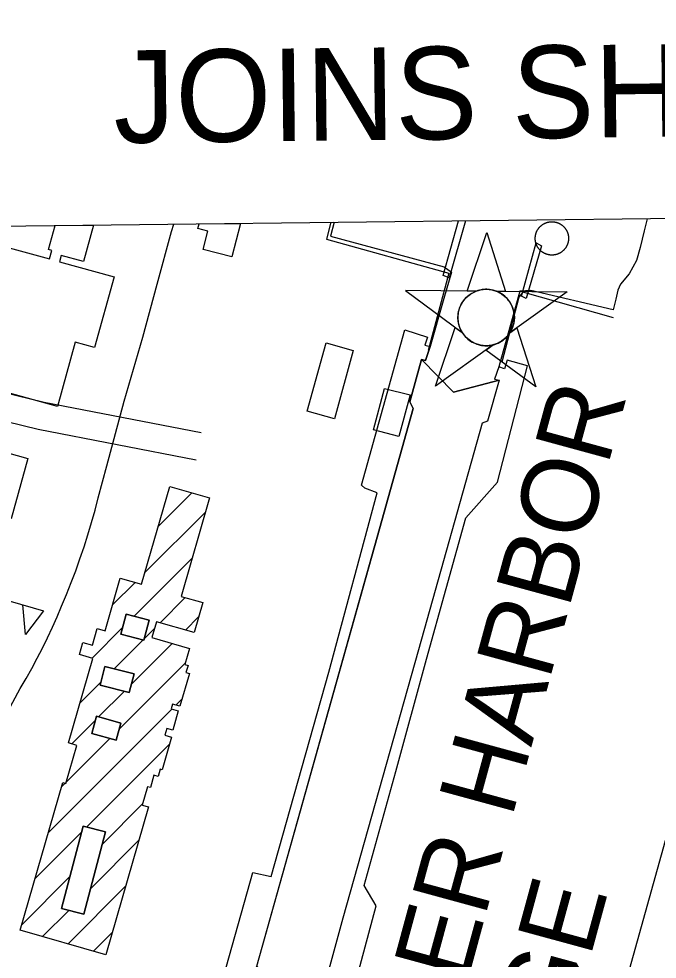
# Model space of a CAD drawing. Extents: x 3677843 to 3715951, y 511991 to 537744.
# Drawn here: x 3694073 to 3694764, y 534934 to 535951 of the extents above; entities that cross this region are included whole.
import ezdxf

# ---------------------------------------------------------------- set-up
doc = ezdxf.new("R2010")
doc.units = 0
for name, color, linetype in [('V-ANNO-TEXT', 7, 'Continuous'), ('V-BLDG-OTLN', 7, 'Continuous'), ('V-CHAN-DOCK', 7, 'Continuous'), ('V-CHAN-NAID', 7, 'Continuous'), ('V-GRID-FRAM', 7, 'Continuous'), ('V-RAIL-TRAK', 7, 'Continuous'), ('V-RIVR-GAGE-IDEN', 7, 'Continuous'), ('V-ROAD-CNTR', 7, 'Continuous'), ('V-RRAP-FSHR', 7, 'Continuous'), ('V-TOPO-SHOR', 7, 'Continuous'), ('V-TRAN-LOCK', 7, 'Continuous')]:
    doc.layers.add(name, color=color, linetype=linetype)

msp = doc.modelspace()

# ---------------------------------------------------------------- linework, layer by layer
at = {"layer": 'V-BLDG-OTLN'}
for p, q in [((3694266.5, 535724.1), (3694267.8, 535729.2)), ((3694267.8, 535729.2), (3694312.6, 535729.7)), ((3694312.6, 535729.7), (3694303.2, 535693.5)), ((3694105, 535701.3), (3694112.2, 535727.4)), ((3694112.2, 535727.4), (3694153.6, 535727.9)), ((3694153.6, 535727.9), (3694142.7, 535688.4)), ((3694277.3, 535721.3), (3694266.5, 535724.1)), ((3694272.2, 535701.5), (3694277.3, 535721.3)), ((3694062.3, 535703.3), (3694106.2, 535691.2)), ((3694108.7, 535700.3), (3694105, 535701.3)), ((3694106.2, 535691.2), (3694108.7, 535700.3)), ((3694303.2, 535693.5), (3694272.2, 535701.5)), ((3694118.6, 535695), (3694116.7, 535688.3)), ((3694116.7, 535688.3), (3694175.9, 535672)), ((3694142.7, 535688.4), (3694118.6, 535695)), ((3694175.9, 535672), (3694154.8, 535595.4)), ((3694133.8, 535601.2), (3694114.7, 535531.8)), ((3694154.8, 535595.4), (3694133.8, 535601.2)), ((3694114.7, 535531.8), (3693912.5, 535587.5)), ((3694223.6, 535401.8), (3694260.2, 535438.4)), ((3694209.3, 535352.1), (3694275, 535417.9)), ((3694197.5, 535305), (3694260.7, 535368.2)), ((3694174.2, 535317.1), (3694198.7, 535341.5)), ((3694041.8, 535327.5), (3694099.4, 535310.6)), ((3694225.6, 535297.7), (3694252.9, 535325)), ((3694253.1, 535289.9), (3694267.4, 535304.2)), ((3694152.1, 535259.6), (3694185.1, 535292.6)), ((3694208.7, 535280.9), (3694219.7, 535291.8)), ((3694176, 535248.1), (3694207.2, 535279.3)), ((3694194.6, 535231.4), (3694238.7, 535275.5)), ((3694181.4, 535182.8), (3694253.1, 535254.5)), ((3694139, 535211.1), (3694161.8, 535233.9)), ((3694159.2, 535196), (3694187.1, 535223.9)), ((3694242.8, 535208.9), (3694249.6, 535215.6)), ((3694104.6, 535070.7), (3694238.5, 535204.6)), ((3694130.1, 535166.8), (3694155.7, 535192.4)), ((3694124.2, 535125.6), (3694171.3, 535172.8)), ((3694146.3, 535077.1), (3694235.9, 535166.6)), ((3694119, 535120.4), (3694122.9, 535124.3)), ((3694163.3, 535058.6), (3694206.8, 535102.2)), ((3694090.3, 535021), (3694140.7, 535071.4)), ((3694150.7, 535010.7), (3694202.7, 535062.7)), ((3694076, 534971.3), (3694128.1, 535023.5)), ((3694126.1, 534950.7), (3694188.4, 535013.1)), ((3694098.6, 534958.6), (3694126.9, 534986.9)), ((3694153.5, 534942.8), (3694174.1, 534963.4))]:
    msp.add_line(p, q, dxfattribs=at)
for points in [[(3694434.7, 535592.3), (3694414.3, 535518.4), (3694384.8, 535526.5), (3694405.2, 535600.4)], [(3694496.2, 535544.2), (3694483.9, 535499.2), (3694456.4, 535506.6), (3694468.5, 535551.3)], [(3694029, 535285.8), (3693894.8, 535323.5), (3693890.9, 535309.5), (3693861.1, 535317.8), (3693876.4, 535372.1), (3693851.4, 535379.1), (3693855.4, 535393.5), (3693880.3, 535386.5), (3693918.2, 535521.6), (3694082.7, 535475.4), (3694064.4, 535410.4), (3693929.1, 535448.5), (3693912, 535387.4), (3694046.9, 535349.4)], [(3694257.6, 535270.2), (3694252.6, 535252.8), (3694255.9, 535251.8), (3694253.7, 535244.1), (3694257.5, 535243), (3694247.2, 535207.6), (3694239, 535209.9), (3694237.6, 535204.9), (3694245.4, 535202.6), (3694239.3, 535181.6), (3694232.9, 535183.4), (3694230.8, 535176.4), (3694238.1, 535174.3), (3694227.9, 535138.9), (3694225.9, 535139.5), (3694223.7, 535131.6), (3694219, 535133), (3694215.2, 535119.7), (3694212.1, 535120.6), (3694206.4, 535100.8), (3694213.1, 535098.8), (3694167, 534938.9), (3694074.3, 534965.6), (3694120.3, 535125), (3694123.7, 535124), (3694135.6, 535165.2), (3694126.5, 535167.9), (3694152.9, 535259.3), (3694138.4, 535263.5), (3694142.2, 535276.7), (3694152.4, 535273.8), (3694157.6, 535291.8), (3694166.2, 535289.3), (3694182.6, 535346.2), (3694205.7, 535339.5), (3694236.2, 535445.3), (3694279.3, 535432.8), (3694248.6, 535326.3), (3694271.8, 535319.6), (3694262.5, 535287.2), (3694221.7, 535298.8), (3694216.8, 535281.8)], [(3694099.4, 535310.6), (3694079.9, 535285.1), (3694077.2, 535317.1)], [(3694208.2, 535279.1), (3694214, 535300.6), (3694189, 535307.3), (3694183.2, 535285.7)], [(3694208.2, 535279.1), (3694183.2, 535285.7), (3694189, 535307.3), (3694214, 535300.6)], [(3694197.5, 535242.6), (3694166, 535250.6), (3694160.9, 535230.5), (3694192.4, 535222.5)], [(3694197.5, 535242.6), (3694192.4, 535222.5), (3694160.9, 535230.5), (3694166, 535250.6)], [(3694183.2, 535189.4), (3694156.8, 535196.7), (3694151.7, 535178.2), (3694178.1, 535170.9)], [(3694183.2, 535189.4), (3694178.1, 535170.9), (3694151.7, 535178.2), (3694156.8, 535196.7)], [(3694166.7, 535071.7), (3694142.5, 535078.1), (3694119, 534989), (3694143.3, 534982.6)], [(3694166.7, 535071.7), (3694143.3, 534982.6), (3694119, 534989), (3694142.5, 535078.1)]]:
    msp.add_lwpolyline(points, close=True, dxfattribs=at)
at = {"layer": 'V-CHAN-DOCK'}
for points in [[(3694631.5, 535714), (3694631.6, 535714.4), (3694631.6, 535714.7), (3694631.6, 535715), (3694631.6, 535715.3), (3694631.7, 535715.6), (3694631.7, 535715.9), (3694631.8, 535716.2), (3694631.8, 535716.6), (3694631.9, 535716.9), (3694631.9, 535717.2), (3694632, 535717.5), (3694632.1, 535717.8), (3694632.1, 535718.1), (3694632.2, 535718.4), (3694632.3, 535718.7), (3694632.4, 535719), (3694632.5, 535719.3), (3694632.6, 535719.6), (3694632.7, 535719.9), (3694632.8, 535720.2), (3694633, 535720.5), (3694633.1, 535720.8), (3694633.2, 535721), (3694633.3, 535721.3), (3694633.5, 535721.6), (3694633.6, 535721.9), (3694633.8, 535722.2), (3694633.9, 535722.4), (3694634.1, 535722.7), (3694634.3, 535723), (3694634.4, 535723.2), (3694634.6, 535723.5), (3694634.8, 535723.8), (3694635, 535724), (3694635.1, 535724.3), (3694635.3, 535724.5), (3694635.5, 535724.8), (3694635.7, 535725), (3694635.9, 535725.3), (3694636.1, 535725.5), (3694636.4, 535725.7), (3694636.6, 535726), (3694636.8, 535726.2), (3694637, 535726.4), (3694637.2, 535726.6), (3694637.5, 535726.8), (3694637.7, 535727), (3694638, 535727.2), (3694638.2, 535727.4), (3694638.4, 535727.6), (3694638.7, 535727.8), (3694638.9, 535728), (3694639.2, 535728.2), (3694639.5, 535728.4), (3694639.7, 535728.6), (3694640, 535728.7), (3694640.2, 535728.9), (3694640.5, 535729.1), (3694640.8, 535729.2), (3694641.1, 535729.4), (3694641.4, 535729.5), (3694641.6, 535729.7), (3694641.9, 535729.8), (3694642.2, 535729.9), (3694642.5, 535730), (3694642.8, 535730.2), (3694643.1, 535730.3), (3694643.4, 535730.4), (3694643.7, 535730.5), (3694644, 535730.6), (3694644.3, 535730.7), (3694644.6, 535730.8), (3694644.9, 535730.9), (3694645.2, 535730.9), (3694645.5, 535731), (3694645.8, 535731.1), (3694646.1, 535731.2), (3694646.4, 535731.2), (3694646.7, 535731.3), (3694647, 535731.3), (3694647.3, 535731.4), (3694647.6, 535731.4), (3694648, 535731.4), (3694648.3, 535731.4), (3694648.6, 535731.5), (3694648.9, 535731.5), (3694649.2, 535731.5), (3694649.5, 535731.5), (3694649.8, 535731.5), (3694650.2, 535731.5), (3694650.5, 535731.5), (3694650.8, 535731.5), (3694651.1, 535731.4), (3694651.4, 535731.4), (3694651.7, 535731.4), (3694652, 535731.3), (3694652.4, 535731.3), (3694652.7, 535731.2), (3694653, 535731.2), (3694653.3, 535731.1)], [(3694653.3, 535731.1), (3694653.6, 535731), (3694653.9, 535731), (3694654.2, 535730.9), (3694654.5, 535730.8), (3694654.8, 535730.7), (3694655.1, 535730.6), (3694655.4, 535730.5), (3694655.7, 535730.4), (3694656, 535730.3), (3694656.3, 535730.2), (3694656.6, 535730.1), (3694656.9, 535730), (3694657.2, 535729.8), (3694657.4, 535729.7), (3694657.7, 535729.5), (3694658, 535729.4), (3694658.3, 535729.3), (3694658.6, 535729.1), (3694658.8, 535728.9), (3694659.1, 535728.8), (3694659.4, 535728.6), (3694659.6, 535728.4), (3694659.9, 535728.3), (3694660.1, 535728.1), (3694660.4, 535727.9), (3694660.6, 535727.7), (3694660.9, 535727.5), (3694661.1, 535727.3), (3694661.4, 535727.1), (3694661.6, 535726.9), (3694661.8, 535726.7), (3694662.1, 535726.5), (3694662.3, 535726.2), (3694662.5, 535726), (3694662.7, 535725.8), (3694662.9, 535725.6), (3694663.2, 535725.3), (3694663.4, 535725.1), (3694663.6, 535724.8), (3694663.8, 535724.6), (3694664, 535724.3), (3694664.1, 535724.1), (3694664.3, 535723.8), (3694664.5, 535723.6), (3694664.7, 535723.3), (3694664.8, 535723.1), (3694665, 535722.8), (3694665.2, 535722.5), (3694665.3, 535722.2), (3694665.5, 535722), (3694665.6, 535721.7), (3694665.8, 535721.4), (3694665.9, 535721.1), (3694666, 535720.8), (3694666.2, 535720.5), (3694666.3, 535720.3), (3694666.4, 535720), (3694666.5, 535719.7), (3694666.6, 535719.4), (3694666.7, 535719.1)], [(3694666.7, 535719.1), (3694666.8, 535718.8), (3694666.9, 535718.5), (3694667, 535718.2), (3694667.1, 535717.9), (3694667.1, 535717.6), (3694667.2, 535717.2), (3694667.3, 535716.9), (3694667.3, 535716.6), (3694667.4, 535716.3), (3694667.4, 535716), (3694667.5, 535715.7), (3694667.5, 535715.4), (3694667.5, 535715.1), (3694667.6, 535714.8), (3694667.6, 535714.4), (3694667.6, 535714.1), (3694667.6, 535713.8), (3694667.6, 535713.5), (3694667.6, 535713.2), (3694667.6, 535712.9), (3694667.6, 535712.6), (3694667.6, 535712.2), (3694667.5, 535711.9), (3694667.5, 535711.6), (3694667.5, 535711.3), (3694667.4, 535711), (3694667.4, 535710.7), (3694667.3, 535710.4), (3694667.3, 535710.1), (3694667.2, 535709.8), (3694667.2, 535709.4), (3694667.1, 535709.1), (3694667, 535708.8), (3694666.9, 535708.5), (3694666.8, 535708.2), (3694666.7, 535707.9), (3694666.6, 535707.6), (3694666.5, 535707.3), (3694666.4, 535707), (3694666.3, 535706.7), (3694666.2, 535706.5), (3694666.1, 535706.2), (3694665.9, 535705.9), (3694665.8, 535705.6), (3694665.7, 535705.3), (3694665.5, 535705), (3694665.4, 535704.8), (3694665.2, 535704.5), (3694665.1, 535704.2), (3694664.9, 535703.9), (3694664.7, 535703.7), (3694664.5, 535703.4), (3694664.4, 535703.2), (3694664.2, 535702.9), (3694664, 535702.6), (3694663.8, 535702.4), (3694663.6, 535702.1), (3694663.4, 535701.9), (3694663.2, 535701.7), (3694663, 535701.4), (3694662.8, 535701.2), (3694662.6, 535701), (3694662.4, 535700.7), (3694662.1, 535700.5), (3694661.9, 535700.3), (3694661.7, 535700.1), (3694661.4, 535699.9), (3694661.2, 535699.7), (3694661, 535699.5), (3694660.7, 535699.3), (3694660.5, 535699.1), (3694660.2, 535698.9), (3694660, 535698.7), (3694659.7, 535698.5), (3694659.4, 535698.4), (3694659.2, 535698.2), (3694658.9, 535698), (3694658.6, 535697.9), (3694658.4, 535697.7), (3694658.1, 535697.6), (3694657.8, 535697.4), (3694657.5, 535697.3), (3694657.2, 535697.1), (3694656.9, 535697), (3694656.7, 535696.9), (3694656.4, 535696.8), (3694656.1, 535696.6), (3694655.8, 535696.5), (3694655.5, 535696.4), (3694655.2, 535696.3), (3694654.9, 535696.2), (3694654.6, 535696.1), (3694654.3, 535696.1), (3694654, 535696), (3694653.7, 535695.9), (3694653.4, 535695.8), (3694653.1, 535695.8), (3694652.7, 535695.7), (3694652.4, 535695.7), (3694652.1, 535695.6)], [(3694652.1, 535695.6), (3694651.8, 535695.6), (3694651.5, 535695.5), (3694651.2, 535695.5), (3694650.9, 535695.5), (3694650.6, 535695.5), (3694650.2, 535695.4), (3694649.9, 535695.4), (3694649.6, 535695.4), (3694649.3, 535695.4), (3694649, 535695.4), (3694648.7, 535695.4), (3694648.4, 535695.5), (3694648, 535695.5), (3694647.7, 535695.5), (3694647.4, 535695.6), (3694647.1, 535695.6), (3694646.8, 535695.6), (3694646.5, 535695.7), (3694646.2, 535695.8), (3694645.9, 535695.8), (3694645.6, 535695.9), (3694645.3, 535696), (3694644.9, 535696), (3694644.6, 535696.1), (3694644.3, 535696.2), (3694644, 535696.3), (3694643.7, 535696.4), (3694643.4, 535696.5), (3694643.1, 535696.6), (3694642.9, 535696.7), (3694642.6, 535696.8), (3694642.3, 535697), (3694642, 535697.1), (3694641.7, 535697.2), (3694641.4, 535697.4), (3694641.1, 535697.5), (3694640.9, 535697.7), (3694640.6, 535697.8), (3694640.3, 535698), (3694640.1, 535698.1), (3694639.8, 535698.3), (3694639.5, 535698.5), (3694639.3, 535698.7), (3694639, 535698.8), (3694638.8, 535699), (3694638.5, 535699.2), (3694638.3, 535699.4), (3694638, 535699.6), (3694637.8, 535699.8), (3694637.5, 535700), (3694637.3, 535700.2), (3694637.1, 535700.5), (3694636.9, 535700.7), (3694636.6, 535700.9), (3694636.4, 535701.1), (3694636.2, 535701.4), (3694636, 535701.6), (3694635.8, 535701.8), (3694635.6, 535702.1), (3694635.4, 535702.3), (3694635.2, 535702.6), (3694635, 535702.8), (3694634.8, 535703.1), (3694634.6, 535703.3), (3694634.5, 535703.6), (3694634.3, 535703.9), (3694634.1, 535704.1), (3694634, 535704.4), (3694633.8, 535704.7), (3694633.7, 535705), (3694633.5, 535705.2), (3694633.4, 535705.5), (3694633.2, 535705.8), (3694633.1, 535706.1), (3694633, 535706.4), (3694632.9, 535706.7), (3694632.8, 535707), (3694632.6, 535707.3), (3694632.5, 535707.6), (3694632.4, 535707.8), (3694632.3, 535708.1), (3694632.2, 535708.4), (3694632.2, 535708.8), (3694632.1, 535709.1), (3694632, 535709.4), (3694631.9, 535709.7), (3694631.9, 535710), (3694631.8, 535710.3), (3694631.8, 535710.6), (3694631.7, 535710.9), (3694631.7, 535711.2), (3694631.6, 535711.5), (3694631.6, 535711.8), (3694631.6, 535712.2), (3694631.6, 535712.5), (3694631.6, 535712.8), (3694631.5, 535713.1), (3694631.5, 535713.4), (3694631.5, 535713.7), (3694631.5, 535714)]]:
    msp.add_lwpolyline(points, dxfattribs=at)
at = {"layer": 'V-CHAN-NAID'}
for points in [[(3694567.6, 535656.4), (3694558, 535656.5), (3694579.1, 535720), (3694599.3, 535656.2), (3694589.7, 535656.3), (3694588.2, 535656.8), (3694586.1, 535657.5), (3694584, 535657.9), (3694582, 535658.2), (3694580.8, 535658.3), (3694579.3, 535658.4), (3694577.6, 535658.4), (3694576.2, 535658.3), (3694574.3, 535658.1), (3694572.9, 535657.9), (3694571.1, 535657.5), (3694569.6, 535657.1), (3694568.6, 535656.8)], [(3694567.6, 535656.4), (3694491.1, 535657), (3694552.6, 535611.6), (3694551.5, 535613.5), (3694550.7, 535615.1), (3694549.9, 535617.1), (3694549.2, 535619.1), (3694548.8, 535620.4), (3694548.5, 535622.1), (3694548.2, 535623.5), (3694548, 535625.1), (3694547.9, 535626.9), (3694547.9, 535628.4), (3694548, 535630.5), (3694548.2, 535632.1), (3694548.6, 535634.3), (3694549.1, 535636.2), (3694549.7, 535638.1), (3694550.3, 535639.8), (3694551.1, 535641.4), (3694551.9, 535642.9), (3694552.9, 535644.7), (3694554, 535646.1), (3694555, 535647.4), (3694556, 535648.6), (3694557.3, 535649.9), (3694558.3, 535650.9), (3694560.1, 535652.3), (3694561.3, 535653.1), (3694563, 535654.2), (3694564.7, 535655.1), (3694566.1, 535655.8)], [(3694589.7, 535656.3), (3694666.2, 535655.7), (3694604, 535611.2), (3694604.9, 535612.7), (3694605.9, 535614.5), (3694606.6, 535616.1), (3694607.4, 535618.1), (3694607.9, 535619.9), (3694608.3, 535621.5), (3694608.7, 535623.5), (3694608.9, 535625.1), (3694609, 535627.3), (3694609, 535629.3), (3694608.8, 535631.6), (3694608.5, 535633.3), (3694608, 535635.6), (3694607.4, 535637.7), (3694606.6, 535639.7), (3694606, 535641.1), (3694605, 535643), (3694603.9, 535644.8), (3694602.7, 535646.5), (3694601.4, 535648), (3694600.2, 535649.4), (3694598.5, 535650.9), (3694596.8, 535652.3), (3694595.1, 535653.5), (3694593.2, 535654.6), (3694591.7, 535655.4)], [(3694586, 535598.3), (3694523.8, 535553.8), (3694544.9, 535617.3), (3694552.6, 535611.6), (3694553.3, 535610.6), (3694554.7, 535608.7), (3694555.9, 535607.3), (3694557.3, 535605.8), (3694558.7, 535604.6), (3694560.2, 535603.4), (3694561.6, 535602.4), (3694563.3, 535601.4), (3694565, 535600.5), (3694566.8, 535599.7), (3694568.2, 535599.1), (3694569.8, 535598.6), (3694572.1, 535598), (3694573.6, 535597.7), (3694575.6, 535597.5), (3694577.2, 535597.4), (3694579, 535597.4), (3694580.7, 535597.4), (3694582.4, 535597.6), (3694584.3, 535597.9)], [(3694604, 535611.2), (3694611.8, 535616.8), (3694632.1, 535553), (3694578.2, 535592.7), (3694586, 535598.3), (3694587.7, 535598.8), (3694589.3, 535599.3), (3694591.4, 535600.2), (3694593.2, 535601.1), (3694595, 535602.2), (3694596.8, 535603.5), (3694598.3, 535604.7), (3694599.6, 535605.9), (3694601, 535607.3), (3694602.2, 535608.7), (3694603.3, 535610.2)]]:
    msp.add_lwpolyline(points, close=True, dxfattribs=at)
msp.add_circle((3694578.5, 535627.9), 30.5, dxfattribs=at)
at = {"layer": 'V-GRID-FRAM'}
msp.add_lwpolyline([(3681899.6, 535587.1), (3713561.2, 535950.9), (3713778.1, 517769.3), (3682100.6, 517405.3), (3681899.6, 535587.1)], dxfattribs=at)
at = {"layer": 'V-RAIL-TRAK'}
msp.add_lwpolyline([(3694058.6, 535197.2), (3694074.4, 535226.8), (3694080.8, 535237.5), (3694086.9, 535248.4), (3694092.8, 535259.4), (3694098.5, 535270.5), (3694104, 535281.7), (3694109.3, 535293), (3694114.3, 535304.4), (3694119.2, 535315.8), (3694124.5, 535328.5), (3694129.5, 535341.3), (3694134.4, 535354.1), (3694139, 535367), (3694143.4, 535380), (3694147.6, 535393.1), (3694151.5, 535406.3), (3694155.3, 535419.5), (3694158.7, 535432.8), (3694167.9, 535467.7), (3694177.3, 535502.6), (3694187, 535537.4), (3694197, 535572.1), (3694207.1, 535606.7), (3694222.6, 535663.9), (3694238.2, 535720.9), (3694240.4, 535728.9)], dxfattribs=at)
at = {"layer": 'V-ROAD-CNTR'}
for points in [[(3693896.2, 535586.2), (3694100.3, 535536.5), (3694270.3, 535503.5)], [(3693888.4, 535557.2), (3694093.9, 535507.2), (3694264.6, 535474.1)], [(3694687.6, 533368.4), (3694401.7, 533435.8), (3694379.9, 533445.5), (3694365.8, 533459.6), (3694352.4, 533481.1), (3694347.3, 533497.8), (3694345.3, 533526.4), (3694350.9, 533552.5), (3694377.1, 533638.5), (3694574, 534342.1), (3694720.7, 534876.6), (3694839.9, 535303.8)]]:
    msp.add_lwpolyline(points, dxfattribs=at)
at = {"layer": 'V-RRAP-FSHR'}
for points in [[(3694410.5, 535730.9), (3694405.7, 535712.6), (3694538, 535675.9), (3694515.7, 535592.1)], [(3694716.1, 535627.7), (3694618.3, 535655.3), (3694613.9, 535649.9), (3694595.6, 535579.7)]]:
    msp.add_lwpolyline(points, dxfattribs=at)
at = {"layer": 'V-TOPO-SHOR'}
for points in [[(3694414.1, 535730.9), (3694410, 535715.9), (3694533.1, 535682.8), (3694541, 535676.8)], [(3694752.5, 535734.8), (3694749.5, 535721.5), (3694745.2, 535703.5), (3694741, 535689.7), (3694733.3, 535675), (3694723.7, 535663.9), (3694721, 535657.6), (3694718.8, 535647.8), (3694715.8, 535636.1), (3694626.8, 535657), (3694614.9, 535656.3)], [(3694541, 535676.8), (3694532.7, 535648.4), (3694518, 535596.5)], [(3694614.9, 535656.3), (3694592, 535574.7), (3694587.6, 535561.3), (3694592.5, 535560.1), (3694543, 535547.2), (3694508.4, 535582.4), (3694513, 535581.4), (3694518, 535596.5)]]:
    msp.add_lwpolyline(points, dxfattribs=at)
at = {"layer": 'V-TRAN-LOCK'}
for points in [[(3694556, 535732.5), (3694538.6, 535670.8), (3694531.8, 535673.3), (3694548.5, 535732.4)], [(3694616.6, 535651.1), (3694632.4, 535708.5), (3694638.3, 535705.5), (3694621.9, 535648.6), (3694616.6, 535651.1)], [(3694508.4, 535582.4), (3694495.8, 535536.6), (3694499.4, 535529.7), (3694460.6, 535390.4), (3694330.1, 534926.1), (3694283.1, 534760.6), (3694272.8, 534763.3), (3694273.8, 534767.4), (3694290.1, 534827.2), (3694301.4, 534879.4), (3694291.2, 534903.5), (3694326.2, 535027.7), (3694345.9, 535023.4), (3694408.1, 535244.5), (3694460.4, 535438.4), (3694447.1, 535443.4), (3694443.5, 535446.8), (3694490.5, 535614.5), (3694514.9, 535606.8), (3694512.2, 535598.1), (3694518, 535596.5), (3694513, 535581.4), (3694508.4, 535582.4)], [(3694592.5, 535560.1), (3694579.9, 535516), (3694574.2, 535513.6), (3694505.4, 535268.7), (3694423.4, 534978.4), (3694403.8, 534907), (3694378.4, 534821.2), (3694355.5, 534740), (3694372.3, 534736.4), (3694384.3, 534780.9), (3694397.2, 534840), (3694426.2, 534868.2), (3694459.4, 534991.8), (3694446.3, 535013.6), (3694480.7, 535137.2), (3694514, 535258.5), (3694556.6, 535411.2), (3694590.6, 535449.9), (3694623.2, 535575.8), (3694601.2, 535581.8), (3694598.4, 535572.5), (3694592, 535574.7), (3694587.6, 535561.3), (3694592.5, 535560.1)], [(3694508.4, 535582.4), (3694543, 535547.2), (3694592.5, 535560.1)]]:
    msp.add_lwpolyline(points, dxfattribs=at)
msp.add_lwpolyline([(3694592.5, 535560.1), (3694579.9, 535516), (3694574.2, 535513.6), (3694505.4, 535268.7), (3694423.4, 534978.4), (3694403.8, 534907), (3694360.9, 534897.1), (3694330.3, 534926.7), (3694460.6, 535390.4), (3694499.4, 535529.7), (3694495.8, 535536.6), (3694508.4, 535582.4), (3694543, 535547.2)], close=True, dxfattribs=at)

# ---------------------------------------------------------------- texts
at = {"layer": 'V-ANNO-TEXT'}
msp.add_text('JOINS SHEET 90', height=100, rotation=0.6583, dxfattribs=at).set_placement((3694175.8, 535816.6))
at = {"layer": 'V-RIVR-GAGE-IDEN'}
for s, p in [('INNER HARBOR', (3694507.3, 534722.5)), ('GAGE', (3694626.1, 534696.8))]:
    msp.add_text(s, height=83, rotation=74.7623, dxfattribs=at).set_placement(p)

doc.saveas('drawing.dxf')
